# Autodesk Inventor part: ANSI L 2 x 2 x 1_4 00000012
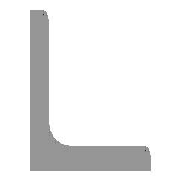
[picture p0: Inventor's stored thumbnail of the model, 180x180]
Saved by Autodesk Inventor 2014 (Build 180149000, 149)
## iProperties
IsCustomPart: 1
Created: 2007-02
Part Number: ANSI L 2 x 2 x 1_4 00000012
Material: Steel, Mild
Document SubType Name: Modeling
Standard: AISC
Designer: Autodesk, Inc.
Size Designation: L 2 x 2 x 1/4
Stock Number: L 2 x 2 x 1/4
Density: 7.86 g/cm^3
Description: Angle Steel
Standards Organization: ANSI
Language: en-US
Categories: <MemberInstance><Categories><Category DisplayName="Structural Shapes" InternalName="089c4875-fa83-4c05-b084-43b9cc11f5ed" Mnemonic="GRDR"><CategoryParameter Dis
Mass: 4986.21 g
Surface Area: 2072.59 cm^2
Volume: 634.378 cm^3
Appearance: Steel
_FrameMemberDoc: Frame Member File
_Version: 15.0.0
_CCFamilyMember: 11
_CCFamilyDisplayName: ANSI L (Equal angles) - Angle Steel
G_L: 41.500 in
G_W: 2.000 in
G_H: 2.000 in
+66D5F651-6C73-4E54-BC92-21E4DA75EC9E+CUTDETAIL1: Notch
+AB975018-38CB-4017-B372-74A5C2C524EF+CUTDETAIL3: Notch
Author: Autodesk, Inc.
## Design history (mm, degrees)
node "Start plane"
node "End plane"
sketch "Sketch"
  geometry: L1 (50.8, 0)-(0, 0); L2 (0, 0)-(0, 50.8); L3 (0, 50.8)-(3.302, 50.8); L4 (6.35, 47.752)-(6.35, 12.7); L5 (12.7, 6.35)-(47.752, 6.35); L6 (50.8, 3.302)-(50.8, 0); L7 (0, -11.041)-(0, 31.538); L8 (-11.041, 0)-(31.538, 0); L9 (0, 63.926)-(0, -23.536) reference; L10 (-23.536, 0)-(63.926, 0) reference; A1 r 6.35 centre (12.7, 12.7) between (6.35, 12.7) and (12.7, 6.35); A2 r 3.048 centre (3.302, 47.752) between (6.35, 47.752) and (3.302, 50.8); A3 r 3.048 centre (47.752, 3.302) between (50.8, 3.302) and (47.752, 6.35); 3 further points
  constraints: 16 end point, 6 point on circle, 6 point on line, 6 tangent, 4 parallel, 3 centre point, 2 collinear, 1 equal radius, 1 horizontal, 1 perpendicular
  dimensions: "d0" = 50.8 distance between parallel lines of L6 L2 (= G_H); "d1" = 50.8 distance between parallel lines of L3 L1 (= G_H); "d2" = 6.35 distance between parallel lines of L2 L4 (= G_T); "d3" = 6.35 distance between parallel lines of L1 L5 (= G_T); "d10" = 0 distance between parallel lines of L7 L2 (computed from ex); "d11" = 0 distance between parallel lines of L8 L1 (computed from d10); "d14" = 6.35 radius of A1 (= G_IR); "d15" = 3.048 radius of A2 (= G_ER)
extrude "Body" new body sketch "Sketch" stored distance "d4" = 1054.1 (= G_L); taper "d5" = 0 deg
node "Driven Length"
  sketch "Sketch5"
    geometry: L1 (0, 0)-(10, 0) reference
    constraints: 2 end point, 1 horizontal
  workplane "Work Plane8"
  sketch "Sketch6"
    geometry: L1 (-2, 0)-(12, 0) reference; L2 (-2, 1054.1)-(12, 1054.1) reference
    dimensions: "d21" = 1054.1 distance between parallel lines of L1 L2 (derived)
workplane "Work Plane3"
workplane "Work Plane4"
workplane "Work Plane6"
workplane "Work Plane7"
workplane "Work Plane9"
workplane "Work Plane10"
body "Solid1"
sketch "Sketch_1"
  geometry: L1 (50.8, 0)-(0, 0); L2 (0, 0)-(0, 50.8); L3 (0, 50.8)-(3.302, 50.8); L4 (6.35, 47.752)-(6.35, 12.7); L5 (12.7, 6.35)-(47.752, 6.35); L6 (50.8, 3.302)-(50.8, 0); A1 r 3.048 centre (3.302, 47.752) between (6.35, 47.752) and (3.302, 50.8); A2 r 6.35 centre (12.7, 12.7) between (6.35, 12.7) and (12.7, 6.35); A3 r 3.048 centre (47.752, 3.302) between (50.8, 3.302) and (47.752, 6.35)
  constraints: 12 end point, 6 point on circle, 3 centre point
extrude "Extrusion2" cut sketch "Sketch_1" stored distance "d22" = 3.302; taper "d23" = 0 deg
sketch "Sketch_2"
  geometry: L1 (50.8, 0)-(0, 0); L2 (0, 0)-(0, 50.8); L3 (0, 50.8)-(3.302, 50.8); L4 (6.35, 47.752)-(6.35, 12.7); L5 (12.7, 6.35)-(47.752, 6.35); L6 (50.8, 3.302)-(50.8, 0); A1 r 3.048 centre (3.302, 47.752) between (6.35, 47.752) and (3.302, 50.8); A2 r 6.35 centre (12.7, 12.7) between (6.35, 12.7) and (12.7, 6.35); A3 r 3.048 centre (47.752, 3.302) between (50.8, 3.302) and (47.752, 6.35)
  constraints: 12 end point, 6 point on circle, 3 centre point
extrude "Extrusion3" cut sketch "Sketch_2" stored distance "d24" = 3.302; taper "d25" = 0 deg
other parameters: "G_H" = 50.8 [user parameter; used in 2 equation terms], "G_T" = 6.35 [user parameter; used in 2 equation terms], "G_ER" = 3.048 [user parameter; used in 1 equation term], "G_IR" = 6.35 [user parameter; used in 1 equation term], "G_L" = 1054.1 (= d21) [user parameter; used in 1 equation term], "ex" = 0 [user parameter; used in 1 equation term], "G_OFFSET_START" = 0 [user parameter; used in 1 equation term], "G_OFFSET_END" = 0 [user parameter; used in 1 equation term], "d12" = 0 (computed from G_OFFSET_START), "d13" = 1054.1 (= G_OFFSET_END + B_L), "B_L" = 1054.1 [user parameter; used in 1 equation term], "d20" = 90 deg
